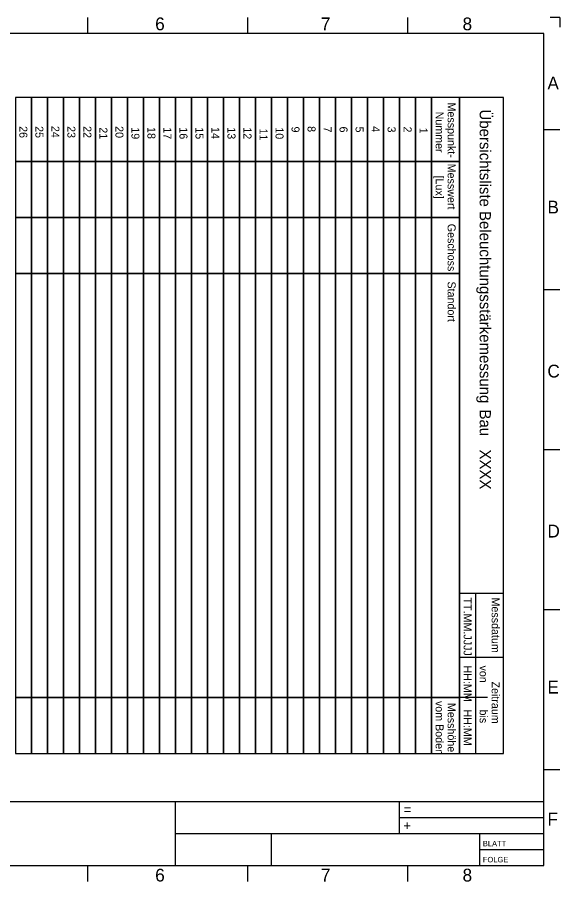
# Model space of a CAD drawing. Extents: x 0 to 395, y 0 to 270.
# Drawn here: x 225.6 to 395, y -0.1 to 270.1 of the extents above; entities that cross this region are included whole.
import ezdxf

# ---------------------------------------------------------------- set-up
doc = ezdxf.new("R2010")
doc.units = 0
doc.layers.add('90_Plankopf', color=7, linetype='Continuous')

msp = doc.modelspace()

# ---------------------------------------------------------------- linework, layer by layer
at = {"layer": '90_Plankopf'}
for p, q in [((247.5, 270), (247.5, 265)), ((297.5, 270), (297.5, 265)), ((347.5, 270), (347.5, 265)), ((395, 270), (392, 270)), ((395, 270), (395, 267)), ((390, 265), (5, 265)), ((390, 5), (390, 265)), ((390, 235), (395, 235)), ((390, 185), (395, 185)), ((390, 135), (395, 135)), ((377.5, 90), (363.75, 90)), ((368.75, 90), (368.75, 40)), ((390, 85), (395, 85)), ((377.5, 70), (363.75, 70)), ((372.5, 57.5), (363.75, 57.5)), ((390, 35), (395, 35)), ((5, 25), (390, 25)), ((275, 5), (275, 25)), ((345, 15), (345, 25)), ((345, 20), (390, 20)), ((275, 15), (390, 15)), ((305, 5), (305, 15)), ((370, 15), (370, 5)), ((370, 10), (390, 10)), ((5, 5), (390, 5)), ((247.5, 5), (247.5, 0)), ((297.5, 5), (297.5, 0)), ((347.5, 5), (347.5, 0))]:
    msp.add_line(p, q, dxfattribs=at)
for points in [[(225, 245), (225, 225), (230, 225), (230, 245)], [(230, 245), (230, 225), (235, 225), (235, 245)], [(235, 245), (235, 225), (240, 225), (240, 245)], [(240, 245), (240, 225), (245, 225), (245, 245)], [(245, 245), (245, 225), (250, 225), (250, 245)], [(250, 245), (250, 225), (255, 225), (255, 245)], [(255, 245), (255, 225), (260, 225), (260, 245)], [(260, 245), (260, 225), (265, 225), (265, 245)], [(265, 245), (265, 225), (270, 225), (270, 245)], [(270, 245), (270, 225), (275, 225), (275, 245)], [(275, 245), (275, 225), (280, 225), (280, 245)], [(280, 245), (280, 225), (285, 225), (285, 245)], [(285, 245), (285, 225), (290, 225), (290, 245)], [(290, 245), (290, 225), (295, 225), (295, 245)], [(295, 245), (295, 225), (300, 225), (300, 245)], [(300, 245), (300, 225), (305, 225), (305, 245)], [(305, 245), (305, 225), (310, 225), (310, 245)], [(310, 245), (310, 225), (315, 225), (315, 245)], [(315, 245), (315, 225), (320, 225), (320, 245)], [(320, 245), (320, 225), (325, 225), (325, 245)], [(325, 245), (325, 225), (330, 225), (330, 245)], [(330, 245), (330, 225), (335, 225), (335, 245)], [(335, 245), (335, 225), (340, 225), (340, 245)], [(340, 245), (340, 225), (345, 225), (345, 245)], [(345, 245), (345, 225), (350, 225), (350, 245)], [(350, 245), (350, 225), (355, 225), (355, 245)], [(355, 245), (355, 225), (363.75, 225), (363.75, 245)], [(363.75, 245), (363.75, 40), (377.5, 40), (377.5, 245)], [(225, 225), (225, 207.5), (230, 207.5), (230, 225)], [(230, 225), (230, 207.5), (235, 207.5), (235, 225)], [(235, 225), (235, 207.5), (240, 207.5), (240, 225)], [(240, 225), (240, 207.5), (245, 207.5), (245, 225)], [(245, 225), (245, 207.5), (250, 207.5), (250, 225)], [(250, 225), (250, 207.5), (255, 207.5), (255, 225)], [(255, 225), (255, 207.5), (260, 207.5), (260, 225)], [(260, 225), (260, 207.5), (265, 207.5), (265, 225)], [(265, 225), (265, 207.5), (270, 207.5), (270, 225)], [(270, 225), (270, 207.5), (275, 207.5), (275, 225)], [(275, 225), (275, 207.5), (280, 207.5), (280, 225)], [(280, 225), (280, 207.5), (285, 207.5), (285, 225)], [(285, 225), (285, 207.5), (290, 207.5), (290, 225)], [(290, 225), (290, 207.5), (295, 207.5), (295, 225)], [(295, 225), (295, 207.5), (300, 207.5), (300, 225)], [(300, 225), (300, 207.5), (305, 207.5), (305, 225)], [(305, 225), (305, 207.5), (310, 207.5), (310, 225)], [(310, 225), (310, 207.5), (315, 207.5), (315, 225)], [(315, 225), (315, 207.5), (320, 207.5), (320, 225)], [(320, 225), (320, 207.5), (325, 207.5), (325, 225)], [(325, 225), (325, 207.5), (330, 207.5), (330, 225)], [(330, 225), (330, 207.5), (335, 207.5), (335, 225)], [(335, 225), (335, 207.5), (340, 207.5), (340, 225)], [(340, 225), (340, 207.5), (345, 207.5), (345, 225)], [(345, 225), (345, 207.5), (350, 207.5), (350, 225)], [(350, 225), (350, 207.5), (355, 207.5), (355, 225)], [(355, 225), (355, 207.5), (363.75, 207.5), (363.75, 225)], [(225, 207.5), (225, 190), (230, 190), (230, 207.5)], [(230, 207.5), (230, 190), (235, 190), (235, 207.5)], [(235, 207.5), (235, 190), (240, 190), (240, 207.5)], [(240, 207.5), (240, 190), (245, 190), (245, 207.5)], [(245, 207.5), (245, 190), (250, 190), (250, 207.5)], [(250, 207.5), (250, 190), (255, 190), (255, 207.5)], [(255, 207.5), (255, 190), (260, 190), (260, 207.5)], [(260, 207.5), (260, 190), (265, 190), (265, 207.5)], [(265, 207.5), (265, 190), (270, 190), (270, 207.5)], [(270, 207.5), (270, 190), (275, 190), (275, 207.5)], [(275, 207.5), (275, 190), (280, 190), (280, 207.5)], [(280, 207.5), (280, 190), (285, 190), (285, 207.5)], [(285, 207.5), (285, 190), (290, 190), (290, 207.5)], [(290, 207.5), (290, 190), (295, 190), (295, 207.5)], [(295, 207.5), (295, 190), (300, 190), (300, 207.5)], [(300, 207.5), (300, 190), (305, 190), (305, 207.5)], [(305, 207.5), (305, 190), (310, 190), (310, 207.5)], [(310, 207.5), (310, 190), (315, 190), (315, 207.5)], [(315, 207.5), (315, 190), (320, 190), (320, 207.5)], [(320, 207.5), (320, 190), (325, 190), (325, 207.5)], [(325, 207.5), (325, 190), (330, 190), (330, 207.5)], [(330, 207.5), (330, 190), (335, 190), (335, 207.5)], [(335, 207.5), (335, 190), (340, 190), (340, 207.5)], [(340, 207.5), (340, 190), (345, 190), (345, 207.5)], [(345, 207.5), (345, 190), (350, 190), (350, 207.5)], [(350, 207.5), (350, 190), (355, 190), (355, 207.5)], [(355, 207.5), (355, 190), (363.75, 190), (363.75, 207.5)], [(225, 190), (225, 57.5), (230, 57.5), (230, 190)], [(230, 190), (230, 57.5), (235, 57.5), (235, 190)], [(235, 190), (235, 57.5), (240, 57.5), (240, 190)], [(240, 190), (240, 57.5), (245, 57.5), (245, 190)], [(245, 190), (245, 57.5), (250, 57.5), (250, 190)], [(250, 190), (250, 57.5), (255, 57.5), (255, 190)], [(255, 190), (255, 57.5), (260, 57.5), (260, 190)], [(260, 190), (260, 57.5), (265, 57.5), (265, 190)], [(265, 190), (265, 57.5), (270, 57.5), (270, 190)], [(270, 190), (270, 57.5), (275, 57.5), (275, 190)], [(275, 190), (275, 57.5), (280, 57.5), (280, 190)], [(280, 190), (280, 57.5), (285, 57.5), (285, 190)], [(285, 190), (285, 57.5), (290, 57.5), (290, 190)], [(290, 190), (290, 57.5), (295, 57.5), (295, 190)], [(295, 190), (295, 57.5), (300, 57.5), (300, 190)], [(300, 190), (300, 57.5), (305, 57.5), (305, 190)], [(305, 190), (305, 57.5), (310, 57.5), (310, 190)], [(310, 190), (310, 57.5), (315, 57.5), (315, 190)], [(315, 190), (315, 57.5), (320, 57.5), (320, 190)], [(320, 190), (320, 57.5), (325, 57.5), (325, 190)], [(325, 190), (325, 57.5), (330, 57.5), (330, 190)], [(330, 190), (330, 57.5), (335, 57.5), (335, 190)], [(335, 190), (335, 57.5), (340, 57.5), (340, 190)], [(340, 190), (340, 57.5), (345, 57.5), (345, 190)], [(345, 190), (345, 57.5), (350, 57.5), (350, 190)], [(350, 190), (350, 57.5), (355, 57.5), (355, 190)], [(355, 190), (355, 57.5), (363.75, 57.5), (363.75, 190)], [(225, 57.5), (225, 40), (230, 40), (230, 57.5)], [(230, 57.5), (230, 40), (235, 40), (235, 57.5)], [(235, 57.5), (235, 40), (240, 40), (240, 57.5)], [(240, 57.5), (240, 40), (245, 40), (245, 57.5)], [(245, 57.5), (245, 40), (250, 40), (250, 57.5)], [(250, 57.5), (250, 40), (255, 40), (255, 57.5)], [(255, 57.5), (255, 40), (260, 40), (260, 57.5)], [(260, 57.5), (260, 40), (265, 40), (265, 57.5)], [(265, 57.5), (265, 40), (270, 40), (270, 57.5)], [(270, 57.5), (270, 40), (275, 40), (275, 57.5)], [(275, 57.5), (275, 40), (280, 40), (280, 57.5)], [(280, 57.5), (280, 40), (285, 40), (285, 57.5)], [(285, 57.5), (285, 40), (290, 40), (290, 57.5)], [(290, 57.5), (290, 40), (295, 40), (295, 57.5)], [(295, 57.5), (295, 40), (300, 40), (300, 57.5)], [(300, 57.5), (300, 40), (305, 40), (305, 57.5)], [(305, 57.5), (305, 40), (310, 40), (310, 57.5)], [(310, 57.5), (310, 40), (315, 40), (315, 57.5)], [(315, 57.5), (315, 40), (320, 40), (320, 57.5)], [(320, 57.5), (320, 40), (325, 40), (325, 57.5)], [(325, 57.5), (325, 40), (330, 40), (330, 57.5)], [(330, 57.5), (330, 40), (335, 40), (335, 57.5)], [(335, 57.5), (335, 40), (340, 40), (340, 57.5)], [(340, 57.5), (340, 40), (345, 40), (345, 57.5)], [(345, 57.5), (345, 40), (350, 40), (350, 57.5)], [(350, 57.5), (350, 40), (355, 40), (355, 57.5)], [(355, 57.5), (355, 40), (363.75, 40), (363.75, 57.5)]]:
    msp.add_lwpolyline(points, close=True, dxfattribs=at)

# ---------------------------------------------------------------- texts
for s, height, p in [('6', 4, (268.67, 266)), ('7', 4, (320.42, 266)), ('8', 4, (364.67, 266)), ('A', 4, (391.17, 247.5)), ('B', 4, (391.17, 208.75)), ('C', 4, (391.17, 157.5)), ('D', 4, (391.17, 107.5)), ('E', 4, (391.17, 58.75)), ('=', 3, (346.26, 21)), ('F', 4, (391.17, 17.5)), ('+', 3, (346.19, 16)), ('BLATT', 1.7, (371, 11)), ('FOLGE', 1.7, (371, 6)), ('6', 4, (268.67, 0)), ('7', 4, (320.42, 0)), ('8', 4, (364.67, 0))]:
    msp.add_text(s, height=height, dxfattribs=at).set_placement(p)
for s, height, p in [('Messpunkt-', 2.5, (360, 243.42)), ('Übersichtsliste Beleuchtungsstärkemessung', 3.5, (370, 241.25)), ('Nummer', 2.5, (356.25, 240.58)), (' 26', 2.5, (226.25, 236.98)), (' 25', 2.5, (231.25, 236.98)), (' 24', 2.5, (236.25, 237.05)), (' 23', 2.5, (241.25, 236.98)), (' 22', 2.5, (246.25, 236.98)), (' 21', 2.5, (251.25, 236.6)), (' 20', 2.5, (256.25, 236.98)), (' 19', 2.5, (261.25, 236.6)), (' 18', 2.5, (266.25, 236.69)), (' 17', 2.5, (271.25, 236.6)), (' 16', 2.5, (276.25, 236.6)), (' 15', 2.5, (281.25, 236.6)), (' 14', 2.5, (286.25, 236.67)), (' 13', 2.5, (291.25, 236.6)), (' 12', 2.5, (296.25, 236.6)), (' 11', 2.5, (301.25, 236.23)), (' 10', 2.5, (306.25, 236.6)), (' 9 ', 2.5, (311.25, 236.85)), (' 8 ', 2.5, (316.25, 236.98)), (' 7 ', 2.5, (321.25, 236.85)), (' 6 ', 2.5, (326.25, 236.85)), (' 5 ', 2.5, (331.25, 236.85)), (' 4 ', 2.5, (336.25, 236.98)), (' 3 ', 2.5, (341.25, 236.85)), (' 2 ', 2.5, (346.25, 236.85)), (' 1 ', 2.5, (351.25, 236.48)), ('Messwert', 2.5, (360, 224.31)), ('[Lux]', 2.5, (356.25, 220.6)), ('Geschoss', 2.5, (360, 205.54)), ('Standort', 2.5, (360, 187.5)), ('Bau', 3.5, (370, 147.5)), ('XXXX     ', 3.5, (370, 135)), ('TT.MM.JJJJ', 2.5, (365, 88.75)), ('Messdatum', 2.5, (373.75, 88.75)), ('HH:MM', 2.5, (365, 67.5)), ('von', 2.5, (370, 67.5)), ('Zeitraum', 2.5, (373.75, 62.5)), ('vom Boden', 2.5, (356.25, 56.43)), ('Messhöhe', 2.5, (360, 55.81)), ('HH:MM', 2.5, (365, 53.75)), ('bis', 2.5, (370, 53.75))]:
    msp.add_text(s, height=height, rotation=270, dxfattribs=at).set_placement(p)

doc.saveas('drawing.dxf')
